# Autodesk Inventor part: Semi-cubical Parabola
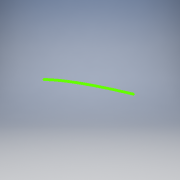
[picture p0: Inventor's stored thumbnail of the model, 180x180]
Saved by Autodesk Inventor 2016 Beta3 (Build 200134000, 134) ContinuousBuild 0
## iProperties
Created: 2008-02
Part Number: Semi-cubical Parabola
Document SubType Name: Modeling
Designer: Autodesk, Inc.
Density: 1 g/cm^3
Material: Generic
Appearance: Default
Author: Autodesk, Inc.
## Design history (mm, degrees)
sketch "Sketch1"
  geometry: 301 further points
  constraints: 301 other
